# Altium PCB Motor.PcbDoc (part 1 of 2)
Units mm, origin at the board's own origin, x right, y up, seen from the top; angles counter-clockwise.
Board outline 48.64 x 60.2 mm, 4 copper layers (Top Layer, VCC, GND, Bottom Layer), stack 0.778 mm thick; 131 components, 120 nets, 670 pads, 289 vias.
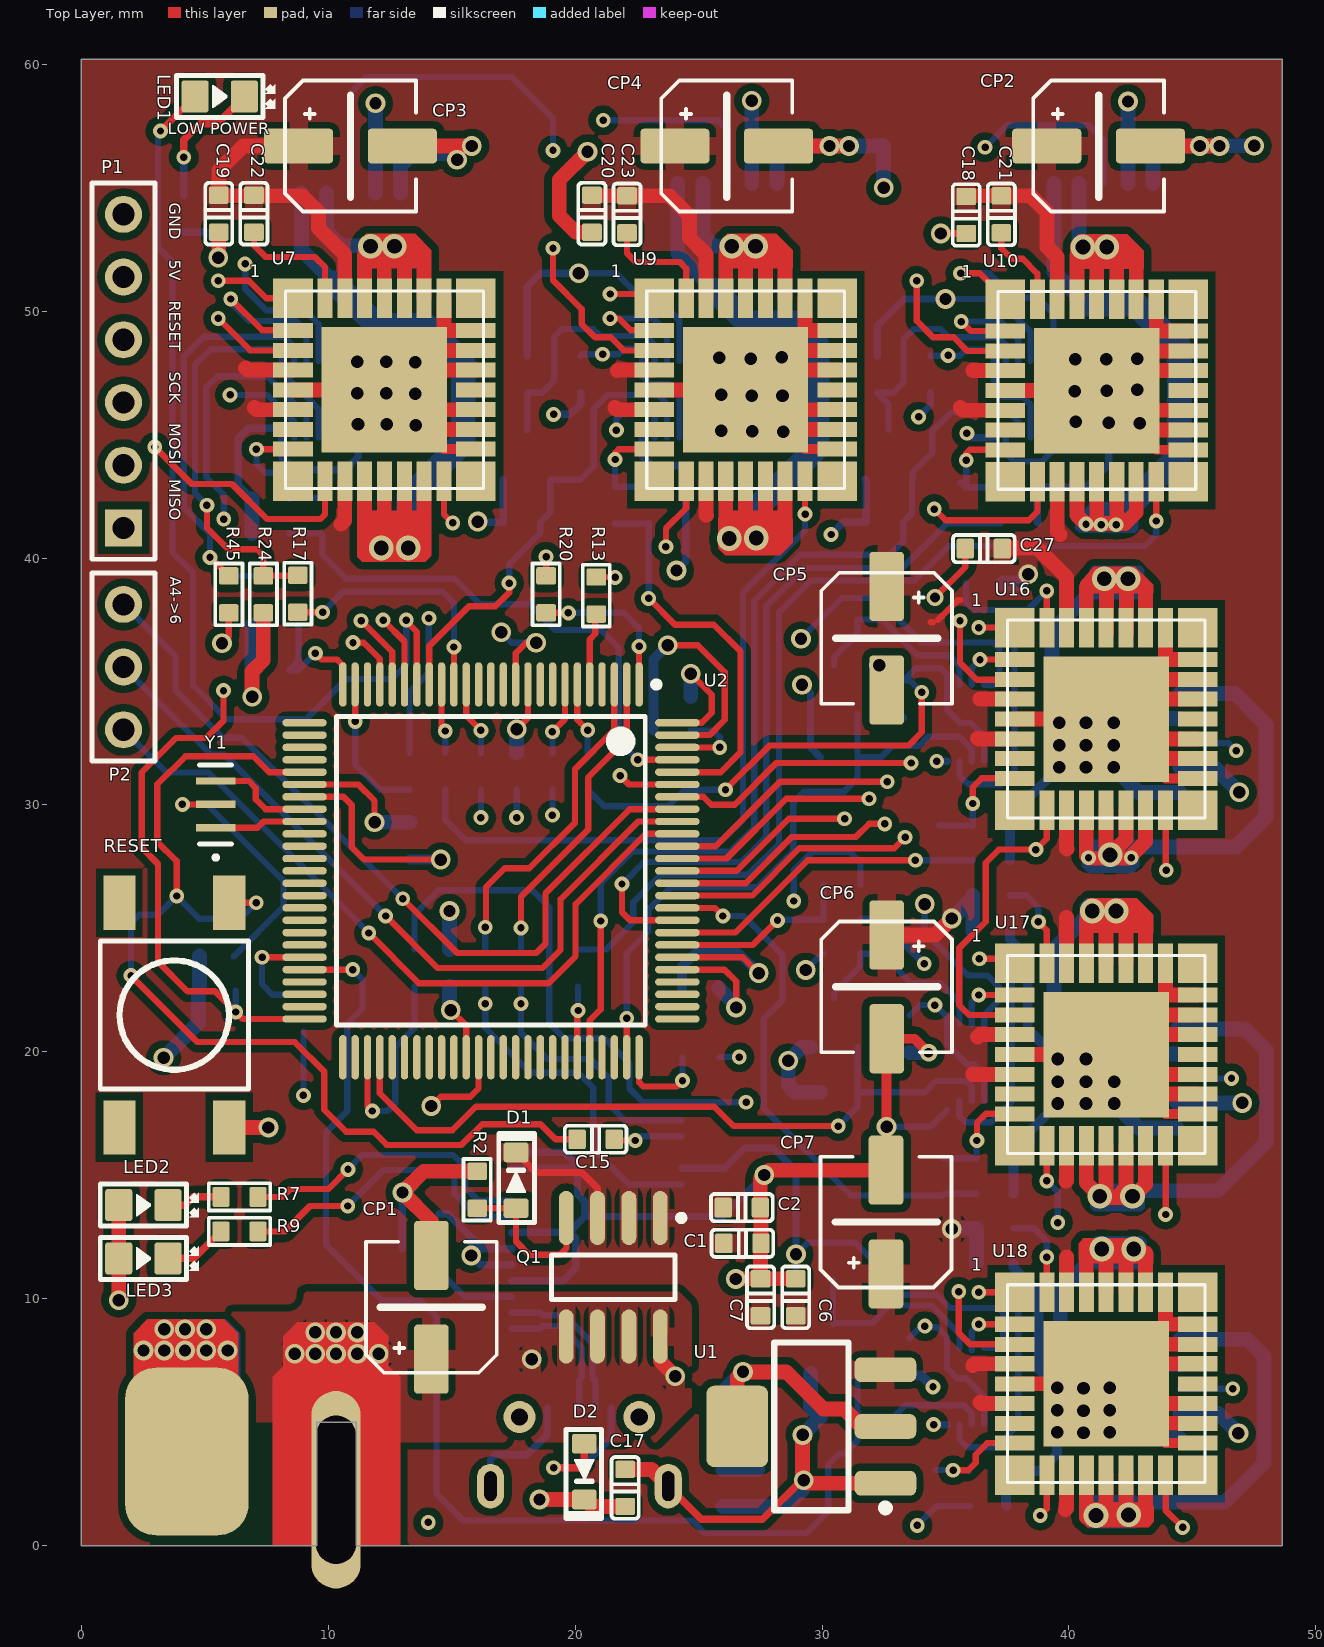
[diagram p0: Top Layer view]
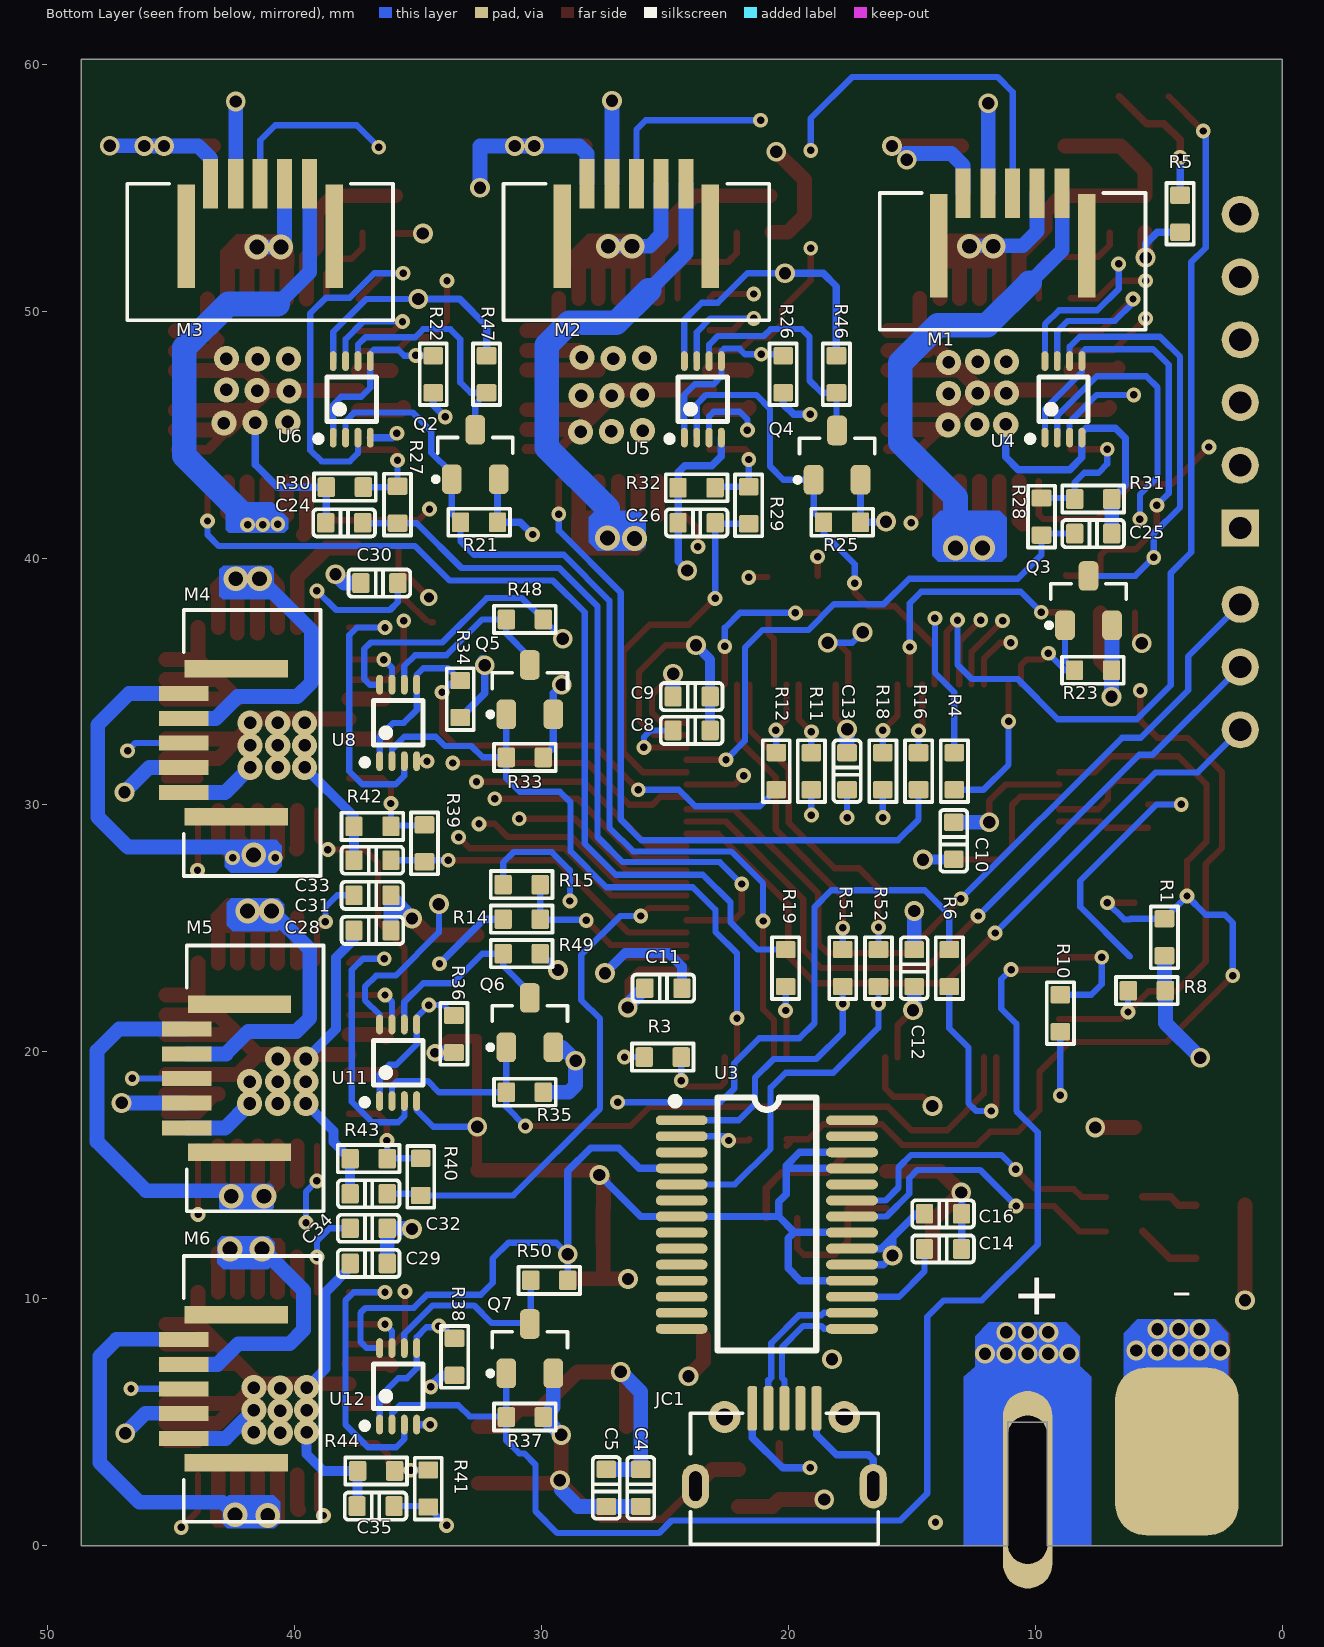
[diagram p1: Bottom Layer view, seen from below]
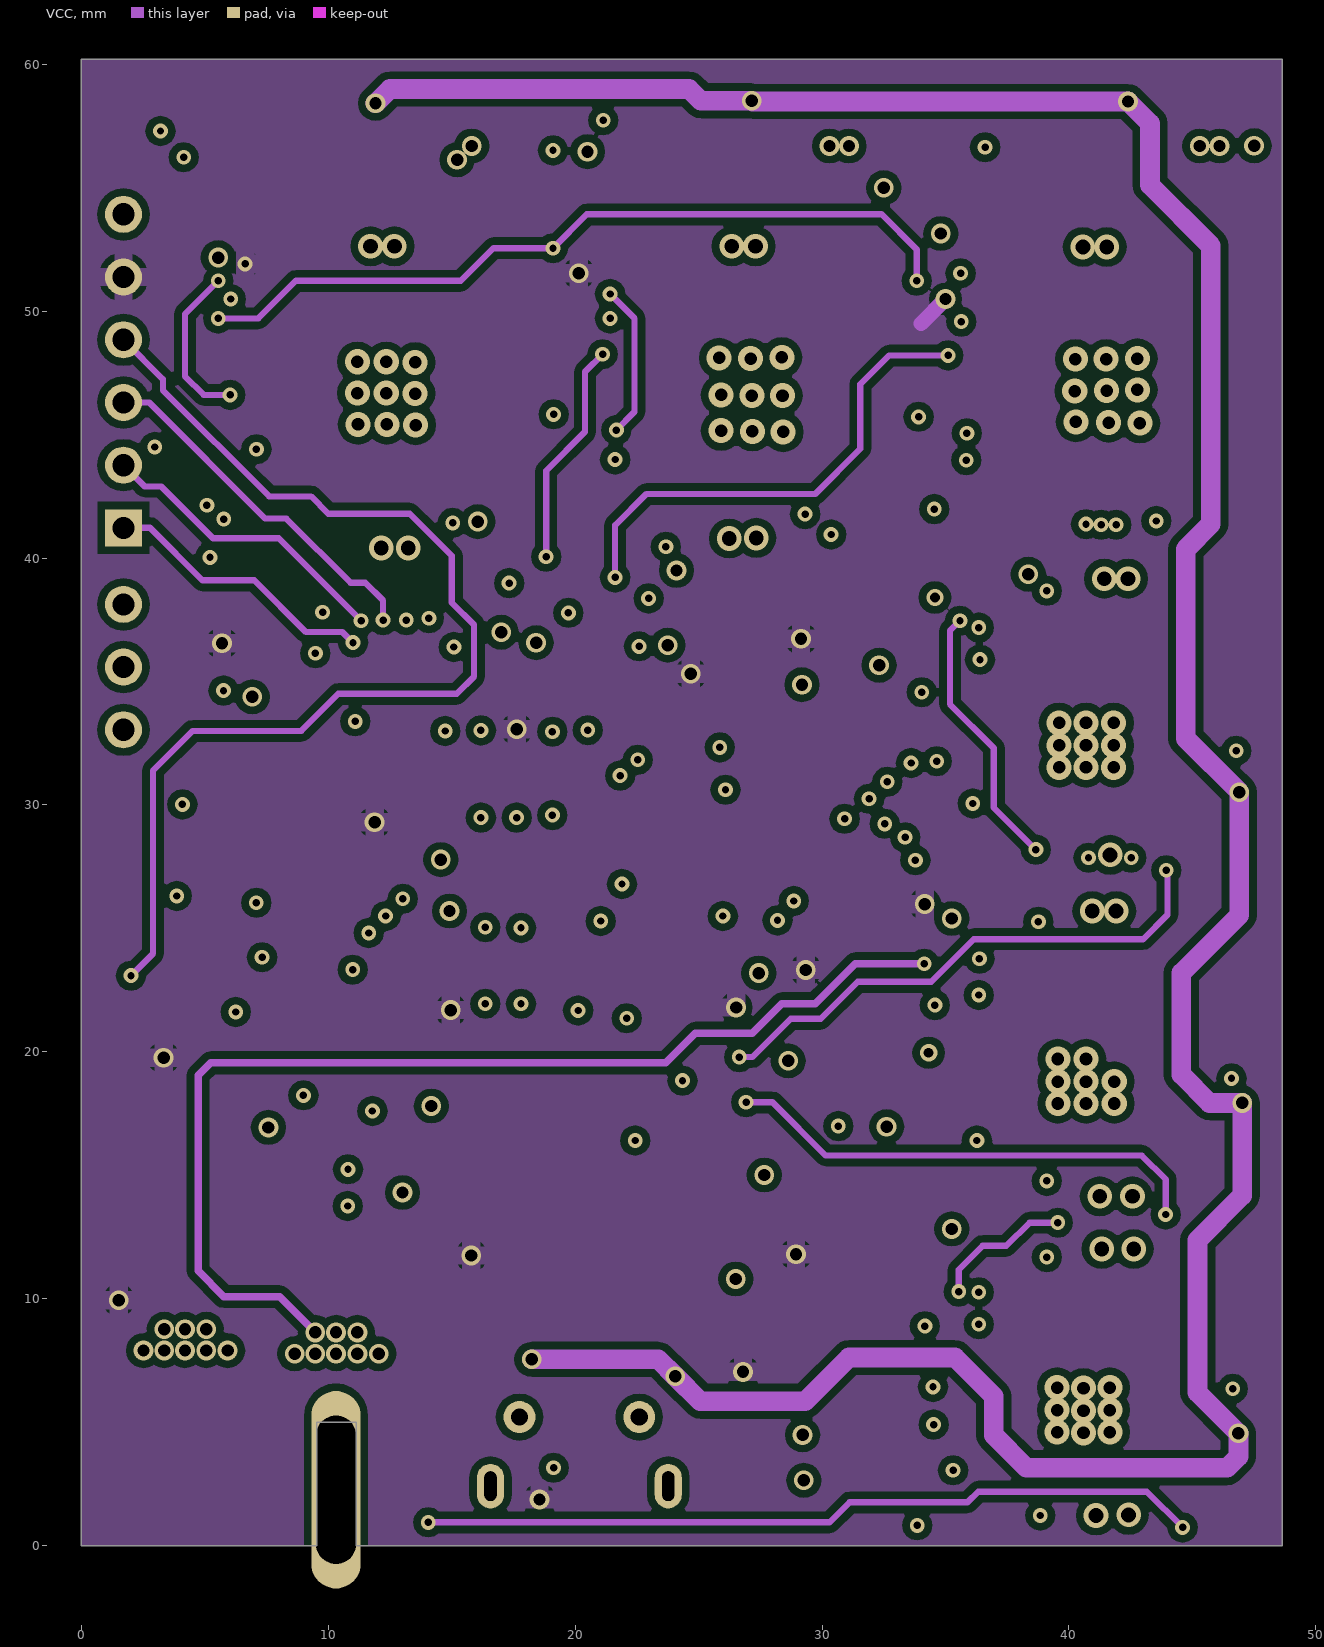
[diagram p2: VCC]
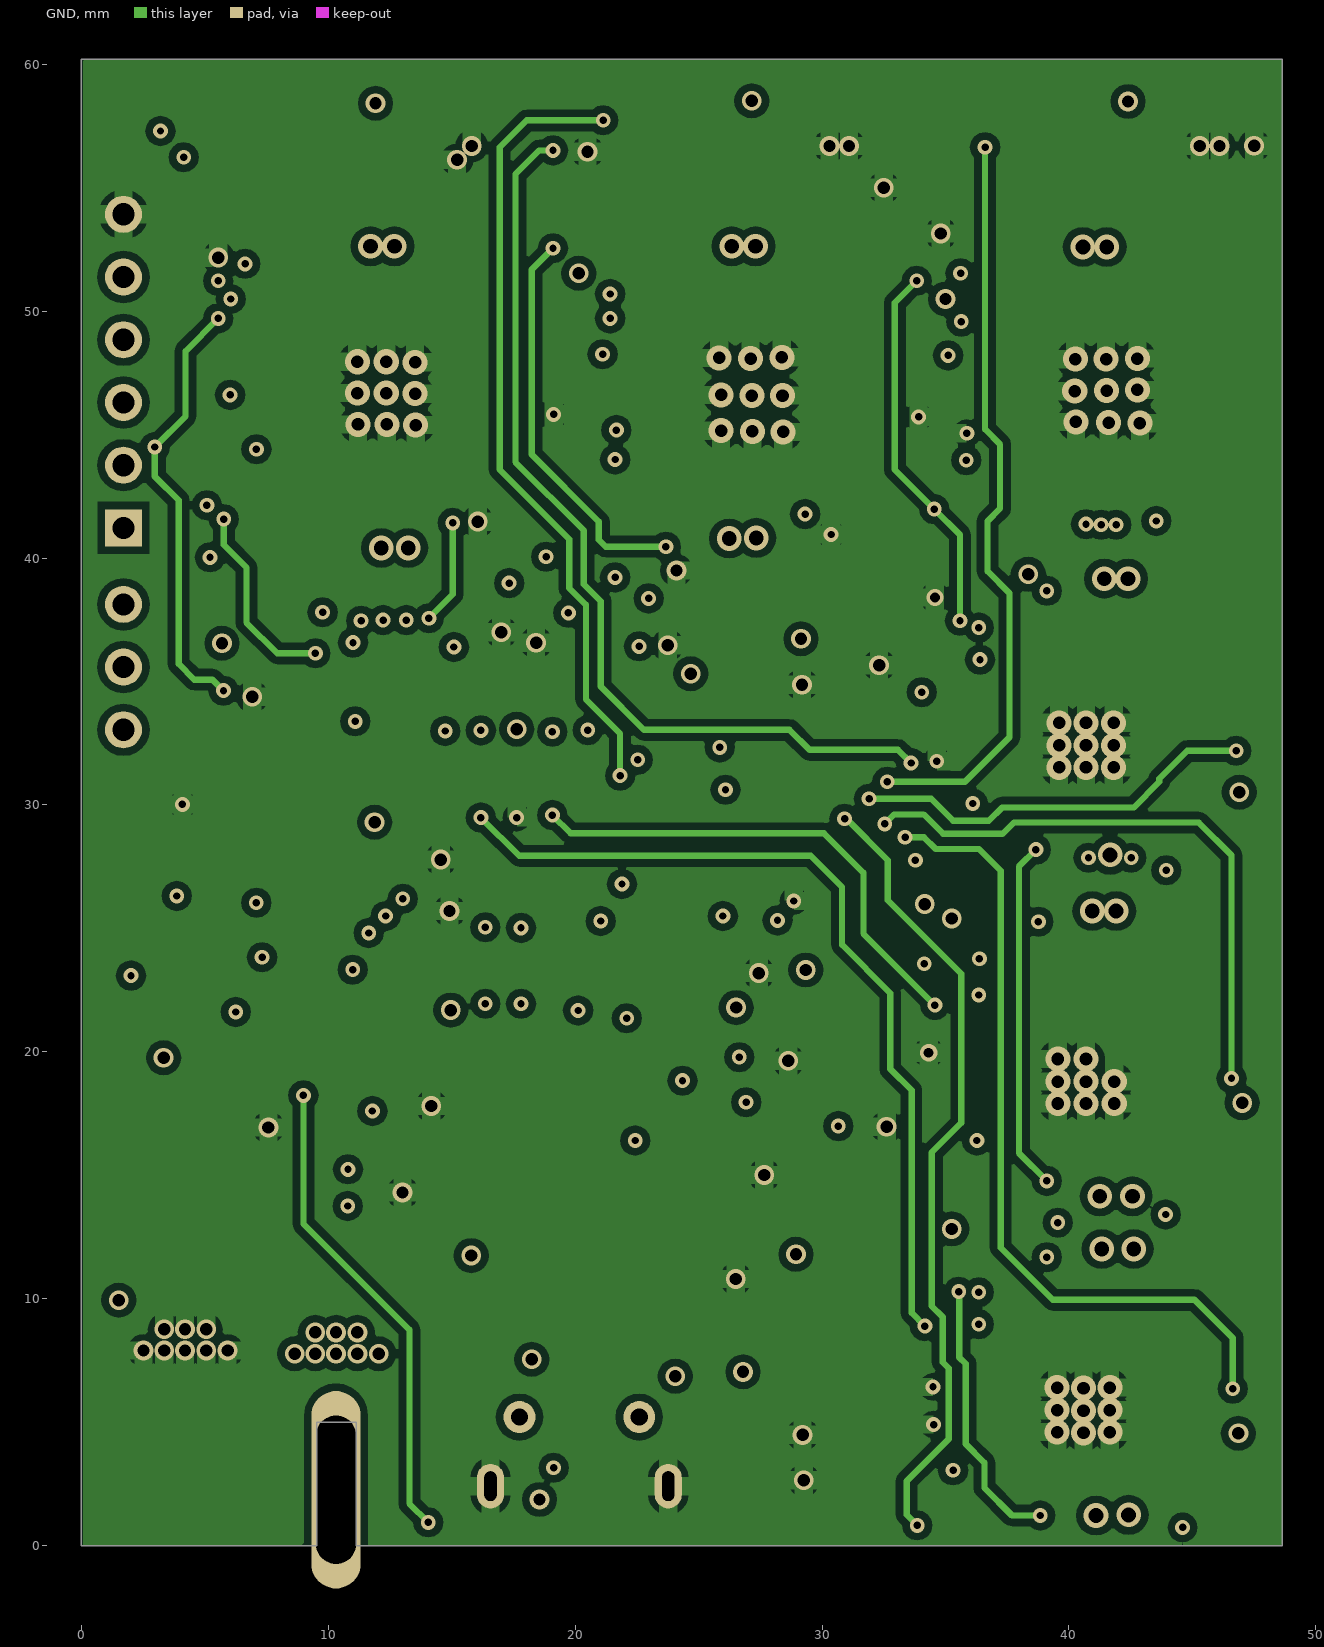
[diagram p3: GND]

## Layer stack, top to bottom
Top Solder: solder mask 0.0102, Solder Resist, Dk 3.5
Top Layer: signal copper 0.0356
Dielectric1: core 0.254, FR-4, Dk 4.2
VCC: signal copper 0.036
Dielectric2: prepreg 0.127, Dk 4.2
GND: signal copper 0.036
Dielectric3: core 0.254, Dk 4.2
Bottom Layer: signal copper 0.0356
Bottom Solder: solder mask 0.0102, Solder Resist, Dk 3.5

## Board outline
0,0 0,60.198 48.641,60.198 48.641,0 11.125,0 11.125,5 9.525,5 9.525,0

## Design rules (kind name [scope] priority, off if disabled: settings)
Clearance Clearance_1 [InPolygon] p1: gap=0.3
Clearance [All] p2: gap=0.178
HoleSize [All] p1: absolutevalues=TRUE maxlimit=7.62 minlimit=0.025 maxpercent=80.000 minpercent=20.000
MinimumSolderMaskSliver [All] p1: minsoldermaskwidth=0.025
PolygonConnect [All] p1: connectstyle=Relief reliefconductorwidth=0.762 reliefentries=4 polygonreliefangle="90 Angle" airgapwidth=0.254
RoutingVias [All] p1: holewidth=0.508 width=2.54 viastyle="Through Hole" minholewidth=0.254 minwidth=0.508 maxholewidth=1.27 maxwidth=1.016
SilkToSilkClearance [All] p1: silktosilkclearance=0.025
SilkToSolderMaskClearance [IsPad] p1: minsilkscreentomaskgap=0 clearancetoexposedcopper=TRUE
SolderMaskExpansion [All] p1: expansion=0.102
Width [All] p1: maxlimit=5.08 minlimit=0.254 preferedwidth=0.254
26 further rules are at their usual default settings.

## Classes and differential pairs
component class Motor: C18 C19 C20 C21 C22 C23 C24 C25 C26 C27 C28 C29 C30 C31 C32 C33 C34 C35 CP2 CP3 CP4 CP5 CP6 CP7 M1 M2 M3 M4 M5 M6 Q2 Q3 Q4 Q5 Q6 Q7 R21 R22 R23 R24 R25 R26 R27 R28 R29 R30 R31 R32 R33 R34 R35 R36 R37 R38 R39 R40 R41 R42 R43 R44 R45 R46 R47 R48 R49 R50 U4 U5 U6 U7 U8 U9 U10 U11 U12 U16 U17 U18
component class Core&Power: C1 C2 C4 C5 C6 C7 C8 C9 C10 C11 C12 C13 C14 C15 C16 C17 CP1 D1 D2 JC1 LED1 LED2 LED3 P1 P2 Q1 R1 R2 R3 R4 R5 R6 R7 R8 R9 R10 R11 R12 R13 R14 R15 R16 R17 R18 R19 R20 R51 R52 RESET U1 U2 U3 Y1

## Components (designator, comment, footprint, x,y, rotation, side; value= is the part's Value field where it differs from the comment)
C1 "105" SM0603C 26.772,12.243 r180 top locked
C2 "105" SM0603C 26.746,13.691 r180 top locked
C4 "106" SM0603C 25.984,2.337 r90 bottom locked
C5 "104" SM0603C 27.381,2.337 r90 bottom locked
C6 "106" SM0603C 28.931,10.058 r270 top locked
C7 "104" SM0603C 27.508,10.058 r270 top locked
C8 "104" SM0603C 23.927,33.02 r0 bottom locked
C9 "104" SM0603C 23.927,34.392 r0 bottom locked
C10 "104" SM0603C 13.31,28.55 r270 bottom locked
C11 "104" SM0603C 25.07,22.581 r180 bottom locked
C12 "104" SM0603C 14.91,23.393 r90 bottom locked
C13 "104" SM0603C 17.628,31.369 r270 bottom locked
C14 "104" SM0603C 13.741,12.014 r180 bottom locked
C15 "104" SM0603C 20.828,16.459 r180 top locked
C16 "104" SM0603C 13.741,13.437 r0 bottom locked
C17 "104" SM0603C 22.022,2.337 r270 top locked
C18 "104" SM0603C 35.839,53.899 r90 top locked
C19 "104" SM0603C 5.563,53.95 r90 top locked
C20 "104" SM0603C 20.676,53.95 r90 top locked
C21 "33nF" SM0603C 37.262,53.924 r270 top locked
C22 "33nF" SM0603C 6.985,53.95 r270 top locked
C23 "33nF" SM0603C 22.098,53.924 r270 top locked
C24 "0.47uF" SM0603C 37.998,41.427 r0 bottom locked
C25 "0.47uF" SM0603C 7.659,40.993 r180 bottom locked
C26 "0.47uF" SM0603C 23.724,41.427 r0 bottom locked
C27 "104" SM0603C 36.551,40.386 r0 top locked
C28 "104" SM0603C 36.855,24.917 r180 bottom locked
C29 "104" SM0603C 37.008,11.43 r180 bottom locked
C30 "33nF" SM0603C 36.576,38.989 r180 bottom locked
C31 "33nF" SM0603C 36.855,26.34 r0 bottom locked
C32 "33nF" SM0603C 37.008,12.852 r0 bottom locked
C33 "0.47uF" SM0603C 36.855,27.762 r0 bottom locked
C34 "0.47uF" SM0603C 37.008,14.249 r0 bottom locked
C35 "0.47uF" SM0603C 36.728,1.6 r0 bottom locked
CP1 "16V 47uF" SMD5-Al 14.173,9.652 r180 top locked
CP2 "16V 47uF" SMD5-Al 41.199,56.693 r90 top locked
CP3 "16V 47uF" SMD5-Al 10.897,56.693 r90 top locked
CP4 "16V 47uF" SMD5-Al 26.137,56.693 r90 top locked
CP5 "16V 47uF" SMD5-Al 32.614,36.754 r0 top locked
CP6 "16V 47uF" SMD5-Al 32.614,22.631 r0 top locked
CP7 "16V 47uF" SMD5-Al 32.588,13.106 r180 top locked
D1 "B5819W" SOD-323 17.602,14.795 r270 top locked
D2 "B5819W" SOD-323 20.371,2.997 r90 top locked
JC1 "Value" MICRO-USB2 20.168,5.207 r180 bottom locked
LED1 "Blue LED" SM0805LED 5.3,57 r180 top
LED2 "Blue LED" SM0805LED 2.21,12.09 r180 top locked
LED3 "Blue LED" SM0805LED 2.21,9.931 r180 top locked
M1 "JC5" FCI_SFW5R-1STE1LF 10.922,57.531 r0 bottom locked
M2 "JC5" FCI_SFW5R-1STE1LF 26.162,57.912 r0 bottom locked
M3 "JC5" FCI_SFW5R-1STE1LF 41.402,57.912 r0 bottom locked
M4 "JC5" FCI_SFW5R-1STE1LF 47.244,32.512 r270 bottom locked
M5 "JC5" FCI_SFW5R-1STE1LF 47.117,18.923 r270 bottom locked
M6 "JC5" FCI_SFW5R-1STE1LF 47.244,6.35 r270 bottom locked
P1 "JC6" HDR1X6 1.702,41.224 r90 top locked
P2 "JC3" HDR1X3 1.702,33.045 r90 top locked
Q1 "Value" SO8_N 21.539,10.871 r270 top locked
Q2 "2N7002" SOT23-3 32.69,44.196 r180 bottom locked
Q3 "2N7002" SOT23-3 7.849,38.278 r180 bottom locked
Q4 "2N7002" SOT23-3 18.034,44.171 r180 bottom locked
Q5 "2N7002" SOT23-3 30.48,34.671 r180 bottom locked
Q6 "2N7002" SOT23-3 30.48,21.184 r180 bottom locked
Q7 "2N7002" SOT23-3 30.48,7.976 r180 bottom locked
R1 "10K" SM0603R 4.775,24.638 r270 bottom locked
R2 "100K" SM0603R 16.027,14.414 r270 top locked
R3 "1k" SM0603R 25.095,19.787 r0 bottom locked
R4 "1k" SM0603R 13.284,31.369 r90 bottom locked
R5 "1k" SM0603R 4.14,53.95 r270 bottom locked
R6 "1k" SM0603R 13.487,23.393 r90 bottom locked
R7 "1k" SM0603R 6.401,14.122 r0 top locked
R8 "1k" SM0603R 5.486,22.479 r0 bottom locked
R9 "1k" SM0603R 6.401,12.725 r0 top locked
R10 "1k" SM0603R 8.992,21.565 r270 bottom locked
R11 "1k" SM0603R 19.075,31.369 r270 bottom locked
R12 "1k" SM0603R 20.498,31.369 r270 bottom locked
R13 "1k" SM0603R 20.853,38.481 r90 top locked
R14 "100K" SM0603R 30.81,25.375 r0 bottom locked
R15 "100K" SM0603R 30.81,26.772 r180 bottom locked
R16 "1k" SM0603R 14.732,31.369 r270 bottom locked
R17 "1k" SM0603R 8.763,38.557 r270 top locked
R18 "1k" SM0603R 16.18,31.369 r90 bottom locked
R19 "1k" SM0603R 20.117,23.393 r90 bottom locked
R20 "1k" SM0603R 18.821,38.532 r90 top locked
R21 "100K" SM0603R 32.537,41.453 r0 bottom locked
R22 "100K" SM0603R 34.392,47.447 r90 bottom locked
R23 "100K" SM0603R 7.671,35.458 r0 bottom locked
R24 "100K" SM0603R 7.366,38.532 r90 top locked
R25 "100K" SM0603R 17.831,41.453 r0 bottom locked
R26 "100K" SM0603R 20.218,47.447 r90 bottom locked
R27 "1K" SM0603R 35.839,42.164 r90 bottom locked
R28 "1K" SM0603R 9.754,41.681 r90 bottom locked
R29 "1K" SM0603R 21.615,42.139 r90 bottom locked
R30 "220" SM0603R 37.973,42.875 r180 bottom locked
R31 "220" SM0603R 7.659,42.393 r0 bottom locked
R32 "220" SM0603R 23.724,42.85 r180 bottom locked
R33 "100K" SM0603R 30.683,31.928 r0 bottom locked
R34 "100K" SM0603R 33.299,34.29 r90 bottom locked
R35 "100K" SM0603R 30.683,18.364 r0 bottom locked
R36 "100K" SM0603R 33.553,20.726 r90 bottom locked
R37 "100K" SM0603R 30.683,5.207 r0 bottom locked
R38 "100K" SM0603R 33.528,7.645 r90 bottom locked
R39 "1K" SM0603R 34.747,28.448 r90 bottom locked
R40 "1K" SM0603R 34.9,14.935 r90 bottom locked
R41 "1K" SM0603R 34.595,2.311 r90 bottom locked
R42 "220" SM0603R 36.855,29.134 r180 bottom locked
R43 "220" SM0603R 37.008,15.672 r180 bottom locked
R44 "220" SM0603R 36.703,3.023 r180 bottom locked
R45 "10K" SM0603R 5.969,38.532 r270 top locked
R46 "10K" SM0603R 18.059,47.447 r90 bottom locked
R47 "10K" SM0603R 32.233,47.447 r90 bottom locked
R48 "10K" SM0603R 30.683,37.516 r180 bottom locked
R49 "10K" SM0603R 30.81,23.978 r180 bottom locked
R50 "10K" SM0603R 29.693,10.744 r180 bottom locked
R51 "1K" SM0603R 17.805,23.393 r270 bottom locked
R52 "1K" SM0603R 16.358,23.393 r270 bottom locked
RESET "KEY_M" SPNO_SMD 3.759,21.488 r90 top locked
U1 "NCP117-5" SOT223-4 29.566,4.826 r90 top locked
U2 "ATmega2560-16AU" 100A_N 16.586,27.33 r270 top locked
U3 "FT232RL" SSOP-28 20.879,13.005 r270 bottom locked
U4 "74XXX" LC-VSSOP-8_2X2.3X05P 8.865,46.431 r180 bottom locked (schematic designator U1)
U5 "74XXX" LC-VSSOP-8_2X2.3X05P 23.47,46.431 r180 bottom locked
U6 "74XXX" LC-VSSOP-8_2X2.3X05P 37.694,46.431 r180 bottom locked
U7 "MC33962" PQFN32_0P8_8X8_SLUG 12.268,46.812 r0 top locked
U8 "74XXX" LC-VSSOP-8_2X2.3X05P 35.814,33.325 r180 bottom locked
U9 "MC33962" PQFN32_0P8_8X8_SLUG 26.899,46.812 r0 top locked
U10 "MC33962" PQFN32_0P8_8X8_SLUG 41.123,46.787 r0 top locked
U11 "74XXX" LC-VSSOP-8_2X2.3X05P 35.814,19.558 r180 bottom locked
U12 "74XXX" LC-VSSOP-8_2X2.3X05P 35.814,6.452 r180 bottom locked
U16 "MC33962" PQFN32_0P8_8X8_SLUG 41.504,33.477 r0 top locked
U17 "MC33962" PQFN32_0P8_8X8_SLUG 41.504,19.888 r0 top locked
U18 "MC33962" PQFN32_0P8_8X8_SLUG 41.504,6.553 r0 top locked
Y1 "CSTCE16M0V53-R0" OSC_CSTCE16M0V53-R0 5.436,30.023 r90 top locked

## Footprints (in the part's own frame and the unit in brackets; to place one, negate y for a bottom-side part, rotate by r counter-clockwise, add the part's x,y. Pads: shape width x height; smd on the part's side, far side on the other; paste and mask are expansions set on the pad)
100A_N [mm] "Thin QFP, 100-Leads, Body 14x14mm, Pitch 0.5mm, IPC Medium Densit"
  oval 1.8x0.3 smd: 1(-7.55,6) 2(-7.55,5.5) 3(-7.55,5) 4(-7.55,4.5) 5(-7.55,4) 6(-7.55,3.5) 7(-7.55,3) 8(-7.55,2.5) 9(-7.55,2) 10(-7.55,1.5) 11(-7.55,1) 12(-7.55,0.5) 13(-7.55,0) 14(-7.55,-0.5) 15(-7.55,-1) 16(-7.55,-1.5) 17(-7.55,-2) 18(-7.55,-2.5) 19(-7.55,-3) 20(-7.55,-3.5) 21(-7.55,-4) 22(-7.55,-4.5) 23(-7.55,-5) 24(-7.55,-5.5) 25(-7.55,-6) 51(7.55,-6) 52(7.55,-5.5) 53(7.55,-5) 54(7.55,-4.5) 55(7.55,-4) 56(7.55,-3.5) 57(7.55,-3) 58(7.55,-2.5) 59(7.55,-2) 60(7.55,-1.5) 61(7.55,-1) 62(7.55,-0.5) 63(7.55,0) 64(7.55,0.5) 65(7.55,1) 66(7.55,1.5) 67(7.55,2) 68(7.55,2.5) 69(7.55,3) 70(7.55,3.5) 71(7.55,4) 72(7.55,4.5) 73(7.55,5) 74(7.55,5.5) 75(7.55,6)
  oval 0.3x1.8 smd: 26(-6,-7.55) 27(-5.5,-7.55) 28(-5,-7.55) 29(-4.5,-7.55) 30(-4,-7.55) 31(-3.5,-7.55) 32(-3,-7.55) 33(-2.5,-7.55) 34(-2,-7.55) 35(-1.5,-7.55) 36(-1,-7.55) 37(-0.5,-7.55) 38(0,-7.55) 39(0.5,-7.55) 40(1,-7.55) 41(1.5,-7.55) 42(2,-7.55) 43(2.5,-7.55) 44(3,-7.55) 45(3.5,-7.55) 46(4,-7.55) 47(4.5,-7.55) 48(5,-7.55) 49(5.5,-7.55) 50(6,-7.55) 76(6,7.55) 77(5.5,7.55) 78(5,7.55) 79(4.5,7.55) 80(4,7.55) 81(3.5,7.55) 82(3,7.55) 83(2.5,7.55) 84(2,7.55) 85(1.5,7.55) 86(1,7.55) 87(0.5,7.55) 88(0,7.55) 89(-0.5,7.55) 90(-1,7.55) 91(-1.5,7.55) 92(-2,7.55) 93(-2.5,7.55) 94(-3,7.55) 95(-3.5,7.55) 96(-4,7.55) 97(-4.5,7.55) 98(-5,7.55) 99(-5.5,7.55) 100(-6,7.55)
  silkscreen extent -7.67,-6.25 6.25,6.83, body extent -7,-7 7,7, height 1.2
FCI_SFW5R-1STE1LF [mil]
  rect 24x79 smd: 1(79,108) 2(39,108) 3(0,108) 4(-39,108) 5(-79,108)
  rect 28x165 smd: 6(-118,192) 7(118,192)
  silkscreen extent -212,108 212,326
HDR1X3 [mm] "Connector; Header; 3 Position"
  round 1.5 hole 0.9: 1(0,0) 2(2.54,0) 3(5.08,0)
  silkscreen extent -1.27,-1.27 6.35,1.27
HDR1X6 [mm] "Connector; Header; 5 Position"
  rect 1.5x1.5 hole 0.9: 1(0,0)
  round 1.5 hole 0.9: 2(2.54,0) 3(5.08,0) 4(7.62,0) 5(10.16,0) 6(12.7,0)
  silkscreen extent -1.27,-1.27 13.97,1.27
LC-VSSOP-8_2X2.3X05P [mm]
  oval 0.28x0.8 smd mask+0.051: 1(-0.75,-1.55) 2(-0.25,-1.55) 3(0.25,-1.55) 4(0.75,-1.55) 5(0.75,1.55) 6(0.25,1.55) 7(-0.25,1.55) 8(-0.75,1.55)
  silkscreen extent -1.47,-1.72 1,0.9, body extent -1.01,-1.61 0.99,1.61, height 0.91
MICRO-USB2 [mm]
  oval 1.1x1.8 hole 0.5 slot 1.2 at 90 deg mask+0.05: 0(-3.6,-2.8) 0(3.6,-2.8)
  rrect50% 0.4x1.8 smd mask+0.05: 1(-1.3,0.352) 2(-0.65,0.352) 3(0,0.352) 4(0.65,0.352) 5(1.3,0.352)
  round 1.29 hole 0.7 unplated mask+0.05: 6(-2.425,0) 7(2.425,0)
  silkscreen extent -3.8,-5.15 3.8,0.15, body extent -3.99,-5.23 3.99,0.2, height 2.69
OSC_CSTCE16M0V53-R0 [mm]
  rect 0.3x1.6 smd paste-25.4 mask-25.4: 1(-0.95,0) 2(0,0) 3(0.95,0)
  silkscreen extent -2.22,-0.65 1.6,0.65
PQFN32_0P8_8X8_SLUG [mil]
  rect 63x63 smd: 1(-145.67,146) 9(-145.67,-145.67) 17(146,-145.67) 25(146,146)
  rect 63x24 smd: 2(-145.67,95) 3(-145.67,63) 4(-145.67,32) 5(-145.67,0) 6(-145.67,-31.5) 7(-145.67,-62.99) 8(-145.67,-94.49) 18(146,-94.49) 19(146,-62.99) 20(146,-31.5) 21(146,0) 22(146,32) 23(146,63) 24(146,95)
  rect 24x63 smd: 10(-94.49,-145.67) 11(-62.99,-145.67) 12(-31.5,-145.67) 13(0,-145.67) 14(32,-145.67) 15(63,-145.67) 16(95,-145.67) 26(95,146) 27(63,146) 28(32,146) 29(0,146) 30(-31.5,146) 31(-62.99,146) 32(-94.49,146)
  rect 200x200 smd: 33(0,0)
  silkscreen extent -157,-157 158,158, body extent -158,-158 158,158, height 44
SM0603C [mm]
  rrect20% 0.7x0.8 smd: 1(-0.75,0) 2(0.75,0)
  silkscreen extent -1.25,-0.55 1.25,0.55, body extent -0.76,-0.38 0.76,0.38, height 0.81
SM0603R [mm]
  rrect20% 0.7x0.8 smd: 1(-0.75,0) 2(0.75,0)
  silkscreen extent -1.25,-0.55 1.25,0.55, body extent -0.76,-0.38 0.76,0.38, height 0.81
SM0805LED [mm]
  rrect20% 1.1x1.3 smd: 1(-1.3,-1.7) 2(0.7,-1.7)
  silkscreen extent -2.55,-2.55 1.45,-0.85, body extent -1.4,-2.08 0.8,-1.31, height 0.4
SMD5-Al [mm]
  rrect20% 1.4x2.8 smd: 1(0,2.1) 2(0,-2.1)
  silkscreen extent -2.65,-2.65 2.65,2.65, body extent -2.67,-2.85 2.65,2.85, height 5.41
SO8_N [mm] "SOIC, 8-Leads, Body 4.9x3.9mm, Pitch 1.27mm, IPC Medium Density"
  oval 2.2x0.6 smd: 1(-2.4,1.905) 2(-2.4,0.635) 3(-2.4,-0.635) 4(-2.4,-1.905) 5(2.4,-1.905) 6(2.4,-0.635) 7(2.4,0.635) 8(2.4,1.905)
  silkscreen extent -2.52,-2.5 0.9,2.88, body extent -1.95,-2.45 1.95,2.45, height 1.76
SOD-323 [mm] "Reflow soldering footprint,2.5x1.3mm"
  rrect25% 0.8x1 smd: 1(-1.13,0) 2(1.13,0)
  silkscreen extent -1.9,-0.7 1.7,0.75, body extent -1.25,-0.65 1.25,0.65, height 1.01
SOT23-3 [mm] "SOT23, 3-Leads, Body 2.9x1.3mm, Pitch 0.95mm, Lead Span 2.5mm, IPC High Density"
  rrect50% 0.8x1.2 smd mask+0.08: 1(-0.95,-1) 2(0.95,-1) 3(0,1)
  silkscreen extent -1.7,-1.1 1.52,0.69, body extent -1.47,-1.14 1.47,1.14, height 1.02
SOT223-4 [mm] "SOT223, 4-Leads, Body 6.5x3.5mm, Pitch 2.3mm, Lead Span 7mm, IPC High Density"
  rrect50% 1x2.5 smd mask+0.08: 1(-2.3,-3) 2(0,-3) 3(2.3,-3)
  rrect25% 3.3x2.5 smd mask+0.08: 4(0,3)
  silkscreen extent -3.45,-3.15 3.4,1.5, body extent -3.35,-3.48 3.35,3.48, height 1.7
SPNO_SMD [mm] "SP NO SMD Tactile switch"
  rect 2.2x1.3 smd: 1(-4.55,-2.225) 2(4.55,-2.225) 3(-4.55,2.225) 4(4.55,2.225)
  silkscreen extent -3,-3 3,3, body extent -4.25,-3.3 4.25,3.3, height 4.32
SSOP-28 [mm]
  oval 0.4x2.1 smd mask+0.051: 1(-4.225,-3.45) 2(-3.575,-3.45) 3(-2.925,-3.45) 4(-2.275,-3.45) 5(-1.625,-3.45) 6(-0.975,-3.45) 7(-0.325,-3.45) 8(0.325,-3.45) 9(0.975,-3.45) 10(1.625,-3.45) 11(2.275,-3.45) 12(2.925,-3.45) 13(3.575,-3.45) 14(4.225,-3.45) 15(4.225,3.45) 16(3.575,3.45) 17(2.925,3.45) 18(2.275,3.45) 19(1.625,3.45) 20(0.975,3.45) 21(0.325,3.45) 22(-0.325,3.45) 23(-0.975,3.45) 24(-1.625,3.45) 25(-2.275,3.45) 26(-2.925,3.45) 27(-3.575,3.45) 28(-4.225,3.45)
  silkscreen extent -5.15,-3.86 5.1,2, body extent -5.16,-3.25 5.11,3.25, height 2.11

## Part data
C1 C2 C4 C5 C6 C7 C8 C9 C10 C11 C12 C13 C14 C15 C16 C17 C18 C19 C20 C21 C22 C23 C24 C25 C26 C27 C28 C29 C30 C31 C32 C33 C34 C35: library part C
CP1 CP2 CP3 CP4 CP5 CP6 CP7: library part 2.1.2.50.5162200, "Cap, 22uF, 20%, 16V"
D1 D2: library part 2.1.4.21.0058190, "Dio, Schottky, B5819W, 1A, 40V, SOD123, SSC"
JC1: library part 2.1.7.20.6780302, "Mini USB Jack, SD-67803-002, Molex"
LED1 LED2 LED3: library part 2.1.4.10.0060330, "LED, Blue, 5mA, 0603"
Q1: "Mos/P"
Q2 Q3 Q4 Q5 Q6 Q7: library part 2.1.4.40.0270020, "Mos/N, 2N7002, 7.5 OHM, 0.5A, SOT23-3, Supertex"
R1 R2 R3 R4 R5 R6 R7 R8 R9 R10 R11 R12 R13 R14 R15 R16 R17 R18 R19 R20 R21 R22 R23 R24 R25 R26 R27 R28 R29 R30 R31 R32 R33 R34 R35 R36 R37 R38 R39 R40 R41 R42 R43 R44 R45 R46 R47 R48 R49 R50 R51 R52: library part RES
U2: "8-bit AVR Microcontroller, 4.5-5.5V, 256KB Flash, 4KB EEPROM, 8KB SRAM, 86 GPIO pins, 100-pin TQFP, Industrial Grade (-40癈 to 85癈), Pb-Free"
Y1: "Ceramic Resonator 16MHz ??0.5% (Tol) ??0.3% (Stability) 15pF 40Ohm 3-Pin CSMD T/R"

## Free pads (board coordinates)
  rrect50% 5x6.8 smd: 0(4.267,3.81)
  rrect50% 5x6.8 smd far side: 0(4.267,3.81)
  oval 2x8 hole 1.6 slot 6 at 90 deg mask+0.05: 1(10.312,2.261)

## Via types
v1: diameter 0.6, hole 0.3, Top Layer to Bottom Layer, tented both sides, 138 vias
v2: diameter 0.8, hole 0.5, Top Layer to Bottom Layer, tented both sides, 75 vias
v3: diameter 1.016, hole 0.508, Top Layer to Bottom Layer, tented both sides, 53 vias
v4: diameter 1, hole 0.6, Top Layer to Bottom Layer, tented both sides, 21 vias
v5: diameter 0.7, hole 0.4, Top Layer to Bottom Layer, tented both sides, 2 vias

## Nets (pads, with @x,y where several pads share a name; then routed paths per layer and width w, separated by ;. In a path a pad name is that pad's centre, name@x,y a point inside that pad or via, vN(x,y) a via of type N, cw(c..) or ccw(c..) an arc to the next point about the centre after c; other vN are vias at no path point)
5VD: C4.2 C5.2 C9.2 C10.1 C11.1 C12.1 C13.1 C16.2 C17.2 D2.1 LED2.2 LED3.2 P1.5 R1.2 R8.1 R45.2 R46.2 R47.2 R48.2 R49.2 R50.2 U1.2 U1.4 U2.10 U2.31 U2.61 U2.80 U2.100 U3.4 U3.19 U3.20 U4.8 U5.8 U6.8 U8.8 U11.8 U12.8 | length 125.3
  Top Layer w0.254: v2(5.69,36.551) 5.969,36.83 R45.2@5.969,37.782 ; U2.31@9.036,30.83 11.207,30.83 11.874,30.163 v2(11.874,29.3) ; v2@14.961,21.869 v2(14.961,21.692) 15.586,21.066 U2.61@15.586,19.78 ; v2(17.628,33.071) 18.086,33.529 U2.10@18.086,34.88 ; U2.80@24.136,23.33 26.047,23.33 26.518,22.86 v2(26.518,21.793) ; U2.100@24.136,33.33 25.126,33.33 25.527,33.731 25.527,34.468 v2(24.677,35.318)
  Top Layer w0.6: v2(1.51,9.943) LED3.2@1.51,11.631 LED2.2@1.51,13.79 ; v2@18.542,1.88 v2(18.554,1.867) D2.1@20.371,1.867 20.651,1.587 C17.2@22.022,1.587 ; U1.4@26.566,4.826 26.566,6.804 v2(26.797,7.036) 28.55,7.036 30.048,5.537 30.886,5.537 31.598,4.826 U1.2@32.566,4.826
  VCC w0.6: 34.006,49.5 v2(35.001,50.495)
  Bottom Layer w0.254: v1(6.629,51.918) 6.629,50.902 7.493,50.038 9.042,50.038 9.615,49.466 U4.8@9.615,47.981 ; v2(20.142,51.537) 21.666,51.537 22.86,50.343 23.52,50.343 24.22,49.644 U5.8@24.22,47.981 ; R50.2@28.943,10.744 v2(28.943,11.798) 29.413,12.268 31.344,12.268 31.979,11.633 31.979,10.643 32.461,10.16 34.646,10.16 35.179,9.627 37.135,9.627 37.338,9.423 37.338,8.255 37.085,8.002 U12.8@36.564,8.002 ; v2@29.083,36.666 R48.2@29.933,37.516 30.797,38.379 32.233,38.379 34.031,36.581 36.927,36.581 37.186,36.322 37.186,35.103 36.958,34.875 U8.8@36.564,34.875 ; v2(29.337,23.317) 29.997,23.978 R49.2@30.06,23.978 ; v2(34.163,25.984) 34.163,24.841 35.916,23.089 36.703,23.089 37.16,22.631 37.16,22.098 36.564,21.502 U11.8@36.564,21.108 ; v2(35.001,50.495) 37.109,50.495 38.444,49.161 U6.8@38.444,47.981
  Bottom Layer w0.3: C16.2@14.491,13.437 14.834,13.437 15.786,12.484 ; U3.19@17.429,11.38 16.154,11.38 v2(15.786,11.747) 15.786,12.484 ; U3.20@17.429,12.03 16.24,12.03 15.786,12.484 ; R46.2@18.059,48.197 18.059,51.003 18.593,51.537 v2(20.142,51.537) ; U3.4@24.329,15.28 26.049,15.28 26.873,16.104 28.016,16.104 28.943,15.177 v2(28.943,11.798) ; R47.2@32.233,48.197 32.233,49.403 33.325,50.495 v2(35.001,50.495)
  Bottom Layer w0.6: v2(3.327,19.761) 4.736,21.17 R8.1@4.736,22.479 4.775,22.518 R1.2@4.775,23.888 ; v2(11.874,29.3) C10.1@13.31,29.3 ; v2@14.91,21.742 C12.1@14.91,22.643 ; C13.1@17.628,32.119 v2(17.628,33.071) ; v2@24.663,35.331 v2(24.677,35.318) C9.2@24.677,34.392 ; C11.1@25.82,22.581 26.518,21.883 v2(26.518,21.793) ; v2(26.797,7.036) 25.984,6.223 C4.2@25.984,3.087 C5.2@27.381,3.087
  other v2: 29.146,36.728
A1: P2.3 U2.93 | length 32.7
  Top Layer w0.254: v1(13.018,26.2) 15.215,24.003 18.415,24.003 18.796,24.384 18.796,26.416 22.21,29.83 U2.93@24.136,29.83
  Bottom Layer w0.254: P2.3@1.702,38.125 3.81,36.017 3.81,34.646 5.728,32.728 6.49,32.728 v1(13.018,26.2)
A2: P2.2 U2.92 | length 31.1
  Top Layer w0.254: v1(12.32,25.502) 14.429,23.393 18.668,23.393 19.406,24.131 19.406,26.187 22.549,29.33 U2.92@24.136,29.33
  Bottom Layer w0.254: P2.2@1.702,35.585 5.258,32.029 5.793,32.029 v1(12.32,25.502)
A3: P2.1 U2.91 | length 30.4
  Top Layer w0.254: v1(11.633,24.816) 13.665,22.784 18.92,22.784 20.015,23.879 20.015,25.984 22.861,28.83 U2.91@24.136,28.83
  Bottom Layer w0.254: P2.1@1.702,33.045 3.429,31.318 5.131,31.318 v1(11.633,24.816)
AREF: C8.2 U2.98 | length 3.4
  Top Layer w0.254: U2.98@24.136,32.33 v1(25.857,32.33)
  Bottom Layer w0.254: C8.2@24.677,33.02 25.578,33.02 25.857,32.741 v1(25.857,32.33)
D2_A: R4.2 U7.16 | length 11.9
  Top Layer w0.254: U7.16@14.681,43.112 14.681,41.783 v1(15.037,41.427)
  GND w0.254: v1(14.072,37.567) 15.037,38.532 v1(15.037,41.427)
  Bottom Layer w0.254: R4.2@13.284,32.119 13.284,34.569 14.072,35.357 v1(14.072,37.567)
D2_B: R16.2 U9.16 | length 28.7
  Top Layer w0.254: v1(29.312,41.783) U9.16@29.312,43.112
  Bottom Layer w0.254: R16.2@14.732,30.619 14.732,29.413 15.57,28.575 25.959,28.575 26.797,29.413 26.797,38.608 29.312,41.123 v1(29.312,41.783)
D2_C: R19.2 U10.16 | length 38.5
  Top Layer w0.254: v1(43.536,41.504) U10.16@43.536,43.087
  Bottom Layer w0.254: R19.2@20.117,24.143 21.248,24.143 22.352,25.248 22.352,26.06 23.47,27.178 27,27.178 28.258,28.435 28.258,37.808 29.54,39.091 33.731,39.091 35.128,40.488 43.078,40.488 43.536,40.945 v1(43.536,41.504)
D2_D: R3.2 U16.16 | length 24.8
  Top Layer w0.254: v1@43.917,27.356 U16.16@43.917,29.777
  VCC w0.254: v1(26.645,19.787) 27.178,19.787 28.727,21.336 29.947,21.336 31.445,22.835 34.417,22.835 36.144,24.562 43.002,24.562 43.993,25.552 43.993,27.305 v1(43.942,27.356)
  Bottom Layer w0.254: R3.2@25.845,19.787 v1(26.645,19.787)
D2_E: R6.2 U17.16 | length 44.6
  Top Layer w0.254: v1(43.917,13.411) U17.16@43.917,16.188
  VCC w0.254: v1(26.924,17.958) 27.991,17.958 30.15,15.799 42.951,15.799 43.917,14.834 v1(43.917,13.411)
  Bottom Layer w0.254: R6.2@13.487,24.143 13.487,25.552 14.478,26.543 18.263,26.543 18.948,25.857 18.948,21.158 19.558,20.549 21.184,20.549 22.2,19.533 22.2,18.517 22.758,17.958 v1(26.924,17.958)
D2_F: R10.2 U18.16 | length 56
  Top Layer w0.254: U18.16@43.917,2.853 43.917,1.422 v1(44.602,0.737)
  VCC w0.254: v1(14.046,0.94) 30.302,0.94 31.115,1.753 35.89,1.753 36.322,2.184 43.155,2.184 v1(44.602,0.737)
  GND w0.254: v1(8.992,18.237) 8.992,13.03 13.284,8.738 13.284,1.702 v1(14.046,0.94)
  Bottom Layer w0.254: v1(8.992,18.237) R10.2@8.992,20.815
DIR_A: Q3.1 R23.2 U2.25 U4.2 | length 24.9
  Top Layer w0.254: v1@5.639,41.707 v1(5.766,41.58) ; v1(9.474,36.144) 9.728,35.89 10.363,35.89 10.586,35.667 U2.25@10.586,34.88
  GND w0.254: v1(5.766,41.58) 5.766,40.538 6.68,39.624 6.68,37.389 7.925,36.144 v1(9.474,36.144)
  Bottom Layer w0.254: v1(5.766,41.58) 5.766,42.57 5.055,43.282 5.055,46.914 5.512,47.371 7.518,47.371 9.115,45.775 U4.2@9.115,44.881 ; Q3.1@8.799,37.278 8.799,35.836 R23.2@8.421,35.458 8.788,35.458 v1(9.474,36.144)
DIR_B: Q4.1 R25.2 U2.18 U5.2 | length 20
  Top Layer w0.254: U2.18@14.086,34.88 14.086,36.438 15.697,38.049 16.764,38.049 17.323,38.608 v1(17.323,38.989)
  Bottom Layer w0.254: v1(17.323,38.989) 17.323,39.751 18.581,41.009 R25.2@18.581,41.453 18.984,41.856 Q4.1@18.984,43.171 20.209,43.171 20.752,43.713 20.752,46.05 21.311,46.609 23.343,46.609 23.72,46.232 U5.2@23.72,44.881
DIR_C: Q2.1 R21.2 U2.71 U6.2 | length 40
  Top Layer w0.254: U2.71@20.586,19.78 20.586,21.272 21.031,21.717 v1(21.031,25.298)
  Bottom Layer w0.254: v1(21.031,25.298) 21.031,26.822 22.327,28.118 26.289,28.118 27.254,29.083 27.254,38.278 29.108,40.132 32.741,40.132 33.287,40.679 R21.2@33.287,41.453 33.64,41.805 Q2.1@33.64,43.196 33.671,43.196 33.671,43.475 34.468,44.272 34.468,45.136 35.23,45.898 37.592,45.898 37.944,45.546 U6.2@37.944,45.013
DIR_D: Q5.1 R33.2 U2.74 U8.2 | length 26.4
  Top Layer w0.254: U2.74@22.086,19.78 v1(22.086,21.361)
  Bottom Layer w0.254: v1(22.086,21.361) 22.086,23.991 22.962,24.867 22.962,25.756 23.876,26.67 27.381,26.67 28.829,28.118 28.829,30.099 29.261,30.531 30.886,30.531 31.433,31.078 R33.2@31.433,31.928 ; Q5.1@31.43,33.671 31.43,31.931 R33.2@31.433,31.928 ; U8.2@36.064,31.775 36.064,32.262 35.56,32.766 34.29,32.766 33.909,32.385 32.842,32.385 32.385,31.928 R33.2@31.433,31.928
DIR_E: Q6.1 R35.2 U2.54 U11.2 | length 30.4
  Top Layer w0.254: U2.54@12.086,19.78 12.086,18.318 13.576,16.828 15.025,16.828 15.977,17.78 25.629,17.78 26.416,16.993 v1(30.658,16.993)
  Bottom Layer w0.254: v1(30.658,16.993) 31.433,17.768 R35.2@31.433,18.364 ; Q6.1@31.43,20.184 31.433,20.18 R35.2@31.433,18.364 ; U11.2@36.064,18.008 36.064,18.597 35.839,18.821 34.62,18.821 34.163,18.364 R35.2@31.433,18.364
DIR_F: Q7.1 R37.2 U2.46 U12.2 | length 55.2
  Top Layer w0.254: U2.46@9.036,23.33 v1(10.985,23.33)
  Bottom Layer w0.254: v1(10.985,23.33) 11.379,22.936 11.379,21.742 10.77,21.133 10.77,17.602 9.906,16.739 9.906,12.192 12.167,9.931 13.716,9.931 14.376,9.271 14.376,2.108 15.469,1.016 24.74,1.016 25.248,0.508 29.362,0.508 30.251,1.397 30.251,3.277 30.709,3.734 30.912,3.734 31.433,4.255 R37.2@31.433,5.207 ; Q7.1@31.43,6.976 31.43,5.21 R37.2@31.433,5.207 ; U12.2@36.064,4.902 36.064,5.363 35.738,5.69 33.376,5.69 32.918,5.232 31.459,5.232 R37.2@31.433,5.207
EN/INV: R8.2 U2.50 U7.3 U7.10 U9.3 U9.10 U10.3 U10.10 U16.3 U16.10 U17.3 U17.10 U18.3 U18.10 | length 204.4
  Top Layer w0.254: v1(2.972,44.501) 4.47,43.002 6.096,43.002 7.518,41.58 9.677,41.58 9.868,41.771 U7.10@9.868,43.112 ; v1(5.537,49.708) 6.833,48.412 U7.3@8.568,48.412 ; v1(5.753,34.633) 5.753,33.414 5.055,32.715 3.835,32.715 2.438,31.318 2.438,28.27 3.099,27.61 3.099,23.647 4.293,22.454 5.41,22.454 v1(6.248,21.615) 6.533,21.33 U2.50@9.036,21.33 ; v1(19.101,52.553) 19.101,51.257 20.269,50.089 20.269,49.479 20.803,48.946 21.438,48.946 21.971,48.412 U9.3@23.199,48.412 ; v1(23.673,40.462) 23.673,41.199 24.499,42.025 U9.10@24.499,43.112 ; v1(33.833,51.232) 33.833,49.606 34.493,48.946 35.331,48.946 35.89,48.387 U10.3@37.423,48.387 ; v1(34.544,41.986) 35.001,41.529 38.367,41.529 38.723,41.885 U10.10@38.723,43.087 ; v1@35.535,10.312 v1(35.535,10.287) 35.535,8.611 35.992,8.153 U18.3@37.804,8.153 ; v1(35.585,37.465) 35.585,35.763 36.271,35.077 U16.3@37.804,35.077 ; U17.3@37.804,21.488 35.966,21.488 35.56,21.895 35.56,24.206 36.627,25.273 36.627,27.661 37.16,28.194 v1(38.659,28.194) 39.104,28.639 U16.10@39.104,29.777 ; v1(38.837,1.219) 39.104,1.486 U18.10@39.104,2.853 ; v1(39.104,14.77) U17.10@39.104,16.188
  VCC w0.254: v1(5.537,49.708) 7.163,49.708 8.687,51.232 15.367,51.232 16.688,52.553 v1(19.101,52.553) 20.472,53.924 32.41,53.924 33.833,52.502 v1(33.833,51.232) ; v1(35.535,10.287) 35.535,11.176 36.5,12.141 37.465,12.141 38.405,13.081 v1(39.548,13.081) ; v1(35.585,37.465) 35.179,37.059 35.179,34.087 36.957,32.309 36.957,29.896 v1(38.659,28.194)
  GND w0.254: v1(5.537,49.708) 4.216,48.387 4.216,45.745 v1(2.972,44.501) 2.972,43.307 3.937,42.342 3.937,35.712 4.572,35.077 5.309,35.077 v1(5.753,34.633) ; v1(19.101,52.553) 18.237,51.689 18.237,44.196 20.955,41.478 20.955,40.742 21.234,40.462 v1(23.673,40.462) ; v1(33.833,51.232) 32.944,50.343 32.944,43.586 v1(34.544,41.986) 35.585,40.945 v1(35.585,37.465) ; v1(35.535,10.287) 35.56,10.262 35.56,7.62 35.814,7.366 35.814,4.115 36.576,3.353 36.576,2.337 37.694,1.219 v1(38.837,1.219) ; v1(38.659,28.194) 37.973,27.508 37.973,15.901 v1(39.104,14.77)
  Bottom Layer w0.254: R8.2@6.236,22.479 6.248,22.467 v1(6.248,21.615) ; v1(39.104,14.77) 39.548,14.326 v1(39.548,13.081)
FB_A: C25.1 R28.1 U2.97 | length 22.2
  Top Layer w0.254: v1(22.534,31.83) U2.97@24.136,31.83
  Bottom Layer w0.254: C25.1@8.409,40.993 9.692,40.993 R28.1@9.754,40.931 9.754,40.132 10.719,39.167 15.113,39.167 16.154,38.125 18.161,38.125 19.202,37.084 21.057,37.084 21.768,36.373 21.768,32.597 v1(22.534,31.83)
FB_B: C26.1 R29.1 U2.96 | length 16
  Top Layer w0.254: v1(22.974,38.367) 24.041,37.3 25.616,37.3 26.695,36.22 26.695,32.131 25.895,31.33 U2.96@24.136,31.33
  Bottom Layer w0.254: R29.1@21.615,41.389 22.935,41.389 C26.1@22.974,41.427 v1(22.974,38.367)
FB_C: C24.1 R27.1 U2.84 | length 30.4
  Top Layer w0.254: v1(21.895,26.797) 21.895,25.654 22.218,25.33 U2.84@24.136,25.33
  Bottom Layer w0.254: v1(21.895,26.797) 22.784,27.686 26.721,27.686 27.737,28.702 27.737,38.049 29.286,39.599 33.249,39.599 35.064,41.414 R27.1@35.839,41.414 37.235,41.414 C24.1@37.248,41.427
FB_D: C33.1 R39.1 U2.83 | length 13.2
  Top Layer w0.254: U2.83@24.136,24.83 26.481,24.83 29.413,27.762 v1(33.782,27.762)
  Bottom Layer w0.254: v1(33.782,27.762) C33.1@36.105,27.762
FB_E: C34.1 R40.1 U2.85 | length 21.7
  Top Layer w0.254: U2.85@24.136,25.83 25.655,25.83 v1(25.984,25.502)
  Bottom Layer w0.254: v1(25.984,25.502) 26.822,25.502 28.397,23.927 28.397,22.098 27.635,21.336 27.635,17.704 31.154,14.185 R40.1@34.9,14.185 34.964,14.249 C34.1@36.258,14.249
FB_F: C35.1 R41.1 U2.88 | length 42.4
  Top Layer w0.254: U2.88@24.136,27.33 26.543,27.33 28.651,29.439 v1(30.912,29.439)
  GND w0.254: v1(30.912,29.439) 30.988,29.439 32.664,27.762 32.664,26.137 35.636,23.165 35.636,17.12 34.442,15.926 34.442,9.703 34.887,9.258 34.887,7.429 35.128,7.188 35.128,4.318 33.426,2.616 33.426,1.245 v1(33.852,0.819)
  Bottom Layer w0.254: v1(33.852,0.819) R41.1@34.595,1.561 34.634,1.6 C35.1@35.978,1.6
